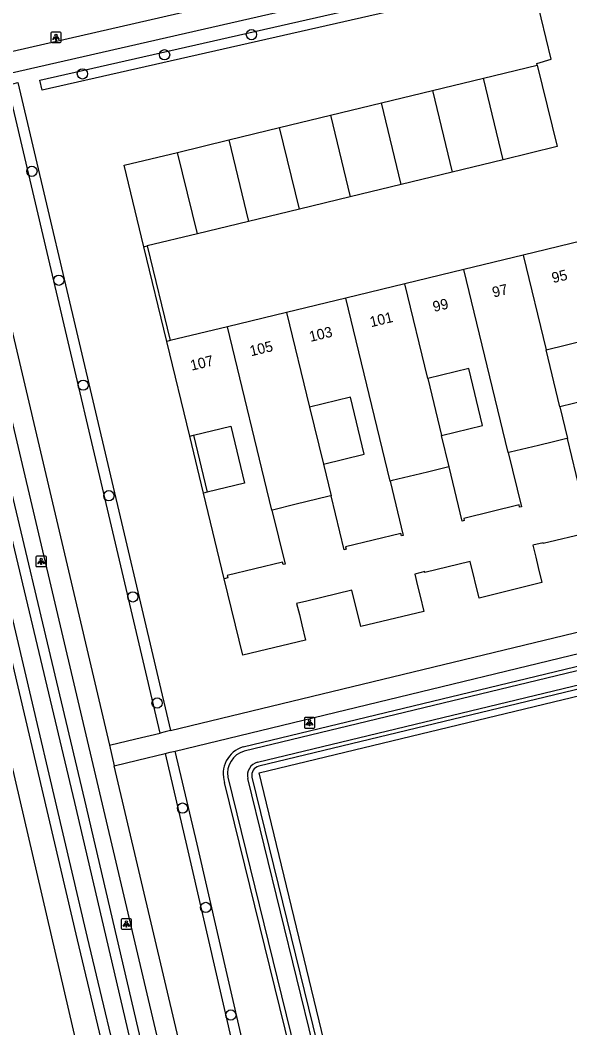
# Model space of a CAD drawing. Extents: x 156664 to 157568, y 383571 to 384421.
# Drawn here: x 156840.7 to 156893.1, y 383982.4 to 384078.5 of the extents above; entities that cross this region are included whole.
import ezdxf

# ---------------------------------------------------------------- set-up
doc = ezdxf.new("R2010")
doc.units = 0
for name, color, linetype in [('IMGEO_Boom', 7, 'Continuous'), ('IMGEO_Groenvoorziening', 7, 'Continuous'), ('IMGEO_Haag', 7, 'Continuous'), ('IMGEO_Hek', 7, 'Continuous'), ('IMGEO_Lichtpunt', 7, 'Continuous'), ('IMGEO_Muur', 7, 'Continuous'), ('IMGEO_Pand', 7, 'Continuous'), ('IMGEO_Pand_nummerreeks', 7, 'Continuous'), ('IMGEO_Rijbaan_lokaal_open', 7, 'Continuous'), ('IMGEO_Voetpad_open', 7, 'Continuous'), ('IMGEO_Waterloop', 7, 'Continuous')]:
    doc.layers.add(name, color=color, linetype=linetype)

msp = doc.modelspace()

# ---------------------------------------------------------------- linework, layer by layer
at = {"layer": 'IMGEO_Boom'}
for centre in [(156862.718, 384077.082), (156854.429, 384075.166), (156846.6, 384073.343), (156841.778, 384064.053), (156844.357, 384053.665), (156846.673, 384043.663), (156849.121, 384033.122), (156851.403, 384023.475), (156853.717, 384013.355), (156856.142, 384003.334), (156858.353, 383993.865), (156860.755, 383983.608)]:
    msp.add_circle(centre, 0.489, dxfattribs=at)
at = {"layer": 'IMGEO_Groenvoorziening'}
for points in [[(156825.282, 384070.084), (156860.158, 383919.98)], [(156836.685, 384046.556), (156846.808, 384004.086), (156865.113, 383925.704)], [(156861.939, 383925.229), (156862.009, 383925.475), (156861.632, 383926.582), (156857.459, 383943.277), (156846.139, 383990.769), (156837.808, 384026.146), (156834.432, 384042.083), (156834.089, 384043.235), (156833.431, 384045.96)], [(156861.913, 384009.165), (156971.048, 384035.487)], [(156965.9, 383938.498), (157002.117, 383942.318), (156972.167, 384033.813), (156964.844, 384031.779), (156863.418, 384007.321)], [(156953.099, 383937.896), (156882.007, 383929.988), (156863.465, 384006.689), (156971.911, 384032.865), (156984.848, 383993.384), (157001.305, 383943.16), (156963.71, 383939.037)], [(156894.839, 384029.59), (156890.551, 384028.557), (156890.532, 384028.636), (156889.551, 384028.393), (156889.825, 384027.259), (156890.057, 384026.288), (156890.416, 384024.833), (156884.421, 384023.366), (156883.565, 384026.863), (156879.257, 384025.815), (156879.24, 384025.884), (156878.288, 384025.653), (156878.565, 384024.519), (156878.792, 384023.543), (156879.155, 384022.083), (156873.159, 384020.64), (156872.305, 384024.119), (156868.004, 384023.082), (156867.027, 384022.845), (156867.284, 384021.787), (156867.53, 384020.811), (156867.878, 384019.352), (156861.885, 384017.92), (156860.113, 384025.202)], [(156862.766, 384006.287), (156881.463, 383929.99)], [(156878.907, 383929.526), (156860.158, 384005.773)]]:
    msp.add_lwpolyline(points, dxfattribs=at)
for centre, radius, start, end in [((156862.687, 384006.614), 2.666, 106.88763, 198.39883), ((156863.612, 384006.476), 0.867, 102.95087, 192.58127)]:
    msp.add_arc(centre, radius, start, end, dxfattribs=at)
at = {"layer": 'IMGEO_Haag'}
for points in [[(156842.768, 384071.784), (156842.547, 384072.759), (156888.556, 384083.206), (156888.777, 384082.231), (156842.768, 384071.784)], [(156854.016, 384010.495), (156839.474, 384072.282), (156840.447, 384072.511), (156854.988, 384010.73)], [(156854.475, 384008.544), (156856.565, 383999.666), (156874.225, 383922.969), (156874.338, 383922.477), (156874.835, 383922.525)], [(156954.665, 383931.279), (156875.116, 383923.557), (156857.538, 383999.895), (156855.447, 384008.779)]]:
    msp.add_lwpolyline(points, dxfattribs=at)
at = {"layer": 'IMGEO_Hek'}
msp.add_lwpolyline([(156953.099, 383937.896), (156882.007, 383929.988), (156863.465, 384006.689), (156971.911, 384032.865), (156984.848, 383993.384), (157001.305, 383943.16)], dxfattribs=at)
at = {"layer": 'IMGEO_Lichtpunt'}
for p, q in [((156843.576, 384077.235), (156843.576, 384076.428)), ((156843.576, 384077.235), (156843.576, 384076.428)), ((156844.478, 384077.33), (156843.67, 384077.33)), ((156844.478, 384077.33), (156843.67, 384077.33)), ((156844.572, 384076.428), (156844.572, 384077.235)), ((156844.572, 384076.428), (156844.572, 384077.235)), ((156843.67, 384076.334), (156844.478, 384076.334)), ((156843.67, 384076.334), (156844.478, 384076.334)), ((156842.167, 384027.259), (156842.167, 384026.452)), ((156842.167, 384027.259), (156842.167, 384026.452)), ((156843.069, 384027.354), (156842.261, 384027.354)), ((156843.069, 384027.354), (156842.261, 384027.354)), ((156843.163, 384026.452), (156843.163, 384027.259)), ((156843.163, 384026.452), (156843.163, 384027.259)), ((156842.261, 384026.358), (156843.069, 384026.358)), ((156842.261, 384026.358), (156843.069, 384026.358)), ((156867.761, 384011.871), (156867.761, 384011.064)), ((156867.761, 384011.871), (156867.761, 384011.064)), ((156868.663, 384011.966), (156867.855, 384011.966)), ((156868.663, 384011.966), (156867.855, 384011.966)), ((156868.757, 384011.064), (156868.757, 384011.871)), ((156868.757, 384011.064), (156868.757, 384011.871)), ((156867.855, 384010.97), (156868.663, 384010.97)), ((156867.855, 384010.97), (156868.663, 384010.97)), ((156850.293, 383992.685), (156850.293, 383991.878)), ((156850.293, 383992.685), (156850.293, 383991.878)), ((156851.195, 383992.78), (156850.387, 383992.78)), ((156851.195, 383992.78), (156850.387, 383992.78)), ((156851.289, 383991.878), (156851.289, 383992.685)), ((156851.289, 383991.878), (156851.289, 383992.685)), ((156850.387, 383991.784), (156851.195, 383991.784)), ((156850.387, 383991.784), (156851.195, 383991.784))]:
    msp.add_line(p, q, dxfattribs=at)
for points in [[(156843.95, 384076.899), (156843.989, 384076.871), (156843.801, 384076.609), (156843.763, 384076.636), (156843.95, 384076.899)], [(156844.052, 384076.851), (156844.099, 384076.851), (156844.099, 384076.529), (156844.052, 384076.529), (156844.052, 384076.851)], [(156844.162, 384076.871), (156844.2, 384076.898), (156844.387, 384076.636), (156844.348, 384076.608), (156844.162, 384076.871)], [(156842.541, 384026.923), (156842.58, 384026.895), (156842.392, 384026.633), (156842.354, 384026.66), (156842.541, 384026.923)], [(156842.643, 384026.875), (156842.69, 384026.875), (156842.69, 384026.553), (156842.643, 384026.553), (156842.643, 384026.875)], [(156842.753, 384026.895), (156842.791, 384026.922), (156842.978, 384026.66), (156842.939, 384026.632), (156842.753, 384026.895)], [(156868.135, 384011.535), (156868.174, 384011.507), (156867.986, 384011.245), (156867.948, 384011.272), (156868.135, 384011.535)], [(156868.237, 384011.487), (156868.284, 384011.487), (156868.284, 384011.165), (156868.237, 384011.165), (156868.237, 384011.487)], [(156868.347, 384011.507), (156868.385, 384011.534), (156868.572, 384011.272), (156868.533, 384011.244), (156868.347, 384011.507)], [(156850.667, 383992.349), (156850.706, 383992.321), (156850.518, 383992.059), (156850.48, 383992.086), (156850.667, 383992.349)], [(156850.769, 383992.301), (156850.816, 383992.301), (156850.816, 383991.979), (156850.769, 383991.979), (156850.769, 383992.301)], [(156850.879, 383992.321), (156850.917, 383992.348), (156851.104, 383992.086), (156851.065, 383992.058), (156850.879, 383992.321)]]:
    msp.add_lwpolyline(points, dxfattribs=at)
for centre in [(156844.075, 384077.033), (156842.666, 384027.057), (156868.26, 384011.669), (156850.792, 383992.483)]:
    msp.add_circle(centre, 0.0994, dxfattribs=at)
for centre, start, end in [((156843.67, 384077.235), 90, 180), ((156843.67, 384077.235), 90, 180), ((156844.478, 384077.235), 0, 90), ((156844.478, 384077.235), 0, 90), ((156843.67, 384076.428), 180, 270), ((156843.67, 384076.428), 180, 270), ((156844.478, 384076.428), 270, 0), ((156844.478, 384076.428), 270, 360), ((156842.261, 384027.259), 90, 180), ((156842.261, 384027.259), 90, 180), ((156843.069, 384027.259), 0, 90), ((156843.069, 384027.259), 0, 90), ((156842.261, 384026.452), 180, 270), ((156842.261, 384026.452), 180, 270), ((156843.069, 384026.452), 270, 0), ((156843.069, 384026.452), 270, 360), ((156867.855, 384011.871), 90, 180), ((156867.855, 384011.871), 90, 180), ((156868.663, 384011.871), 0, 90), ((156868.663, 384011.871), 0, 90), ((156867.855, 384011.064), 180, 270), ((156867.855, 384011.064), 180, 270), ((156868.663, 384011.064), 270, 0), ((156868.663, 384011.064), 270, 360), ((156850.387, 383992.685), 90, 180), ((156850.387, 383992.685), 90, 180), ((156851.195, 383992.685), 0, 90), ((156851.195, 383992.685), 0, 90), ((156850.387, 383991.878), 180, 270), ((156850.387, 383991.878), 180, 270), ((156851.195, 383991.878), 270, 0), ((156851.195, 383991.878), 270, 360)]:
    msp.add_arc(centre, 0.0946, start, end, dxfattribs=at)
at = {"layer": 'IMGEO_Muur'}
for points in [[(156854.648, 384047.837), (156852.46, 384056.86)], [(156852.781, 384056.937), (156854.969, 384047.915)], [(156858.151, 384033.36), (156856.828, 384038.808)], [(156857.188, 384038.894), (156858.51, 384033.448)]]:
    msp.add_lwpolyline(points, dxfattribs=at)
at = {"layer": 'IMGEO_Pand'}
for points in [[(156884.831, 384072.925), (156889.977, 384074.171)], [(156889.977, 384074.171), (156891.875, 384066.406), (156886.706, 384065.154)], [(156879.992, 384071.752), (156884.831, 384072.925)], [(156886.706, 384065.154), (156884.831, 384072.925)], [(156875.124, 384070.573), (156879.992, 384071.752)], [(156879.992, 384071.752), (156881.868, 384063.982)], [(156870.265, 384069.395), (156875.124, 384070.573)], [(156877.001, 384062.803), (156875.124, 384070.573)], [(156865.407, 384068.218), (156870.265, 384069.395)], [(156870.265, 384069.395), (156872.143, 384061.627)], [(156860.547, 384067.041), (156865.407, 384068.218)], [(156867.285, 384060.45), (156865.407, 384068.218)], [(156855.679, 384065.861), (156860.547, 384067.041)], [(156860.547, 384067.041), (156862.428, 384059.274)], [(156852.46, 384056.86), (156850.571, 384064.624), (156855.679, 384065.861)], [(156857.56, 384058.095), (156855.679, 384065.861)], [(156886.706, 384065.154), (156881.868, 384063.982)], [(156881.868, 384063.982), (156877.001, 384062.803)], [(156877.001, 384062.803), (156872.143, 384061.627)], [(156872.143, 384061.627), (156867.285, 384060.45)], [(156867.285, 384060.45), (156862.428, 384059.274)], [(156862.428, 384059.274), (156857.56, 384058.095)], [(156857.56, 384058.095), (156852.781, 384056.937)], [(156894.26, 384057.432), (156888.622, 384056.067)], [(156852.46, 384056.86), (156852.781, 384056.937)], [(156888.622, 384056.067), (156882.984, 384054.701)], [(156888.622, 384056.067), (156890.807, 384047.038)], [(156882.984, 384054.701), (156877.346, 384053.335)], [(156887.214, 384037.228), (156882.984, 384054.701)], [(156877.346, 384053.335), (156871.709, 384051.97)], [(156879.531, 384044.307), (156877.346, 384053.335)], [(156871.709, 384051.97), (156866.071, 384050.604)], [(156875.936, 384034.512), (156871.709, 384051.97)], [(156866.071, 384050.604), (156860.433, 384049.238)], [(156866.071, 384050.604), (156868.257, 384041.576)], [(156860.433, 384049.238), (156854.969, 384047.915)], [(156864.676, 384031.745), (156860.433, 384049.238)], [(156854.969, 384047.915), (156854.648, 384047.837)], [(156856.828, 384038.808), (156854.648, 384047.837)], [(156890.807, 384047.038), (156894.71, 384047.98), (156896.031, 384042.54), (156892.125, 384041.59)], [(156892.125, 384041.59), (156890.807, 384047.038)], [(156880.85, 384038.859), (156884.755, 384039.808), (156883.434, 384045.249), (156879.531, 384044.307)], [(156879.531, 384044.307), (156880.85, 384038.859)], [(156869.577, 384036.128), (156873.479, 384037.077), (156872.158, 384042.518), (156868.257, 384041.576)], [(156868.257, 384041.576), (156869.577, 384036.128)], [(156892.125, 384041.59), (156892.851, 384038.588)], [(156857.188, 384038.894), (156860.736, 384039.751), (156862.057, 384034.31), (156858.51, 384033.448)], [(156898.483, 384039.975), (156899.739, 384034.784), (156899.571, 384034.743), (156899.522, 384034.965), (156894.235, 384033.695), (156894.286, 384033.473), (156894.099, 384033.43), (156892.851, 384038.588)], [(156856.828, 384038.808), (156857.188, 384038.894)], [(156881.572, 384035.877), (156880.85, 384038.859)], [(156892.851, 384038.588), (156892.674, 384038.545), (156891.521, 384038.267), (156890.103, 384037.925), (156887.402, 384037.273), (156887.214, 384037.228)], [(156887.214, 384037.228), (156888.461, 384032.074), (156888.288, 384032.032), (156888.236, 384032.244), (156882.959, 384030.955), (156883.007, 384030.744), (156882.826, 384030.698), (156881.572, 384035.877)], [(156869.577, 384036.128), (156870.306, 384033.116)], [(156881.572, 384035.877), (156881.404, 384035.836), (156879.649, 384035.411), (156878.826, 384035.212), (156876.127, 384034.558), (156875.936, 384034.512)], [(156875.936, 384034.512), (156877.19, 384029.332), (156877.025, 384029.29), (156876.967, 384029.517), (156871.689, 384028.239), (156871.74, 384028.012), (156871.553, 384027.964), (156870.306, 384033.116)], [(156858.51, 384033.448), (156858.151, 384033.36)], [(156860.113, 384025.202), (156858.151, 384033.36)], [(156870.306, 384033.116), (156870.137, 384033.075), (156866.856, 384032.276), (156864.861, 384031.79), (156864.676, 384031.745)], [(156864.676, 384031.745), (156865.924, 384026.6), (156865.746, 384026.556), (156865.691, 384026.781), (156860.413, 384025.519), (156860.467, 384025.284), (156860.113, 384025.202)]]:
    msp.add_lwpolyline(points, dxfattribs=at)
at = {"layer": 'IMGEO_Rijbaan_lokaal_open'}
msp.add_lwpolyline([(156889.977, 384074.171), (156889.94, 384074.329), (156891.301, 384074.755), (156888.906, 384084.645)], dxfattribs=at)
at = {"layer": 'IMGEO_Voetpad_open'}
for points in [[(156888.427, 384086.586), (156811.028, 384068.852)], [(156888.906, 384084.645), (156834.367, 384072.163)], [(156832.423, 384071.718), (156867.866, 383921.383), (156867.979, 383920.714)], [(156834.367, 384072.163), (156849.171, 384009.324)], [(156855.447, 384008.779), (156971.462, 384036.848)], [(156854.988, 384010.73), (156961.888, 384036.567)], [(156849.171, 384009.324), (156851.701, 384009.935), (156854.016, 384010.495)], [(156854.988, 384010.73), (156854.502, 384010.612), (156854.016, 384010.495)], [(156849.171, 384009.324), (156849.631, 384007.372)], [(156849.631, 384007.372), (156851.846, 384007.908), (156854.475, 384008.544)], [(156854.475, 384008.544), (156854.961, 384008.661), (156855.447, 384008.779)], [(156870.13, 383920.364), (156849.631, 384007.372)]]:
    msp.add_lwpolyline(points, dxfattribs=at)
at = {"layer": 'IMGEO_Waterloop'}
for points in [[(156834.425, 384045.9), (156835.009, 384043.483), (156835.356, 384042.318), (156838.738, 384026.354), (156847.066, 383990.989), (156858.384, 383943.503), (156862.546, 383926.851), (156862.901, 383925.812), (156863.002, 383925.486)], [(156845.881, 384003.867), (156835.811, 384046.116)], [(156971.146, 384035.093), (156862.02, 384008.774)], [(156863.303, 384007.711), (156964.742, 384032.172), (156972.432, 384034.308), (157002.659, 383941.967), (156965.949, 383938.095)], [(156860.453, 384006.276), (156879.298, 383929.636)], [(156881.069, 383929.893), (156862.381, 384006.152)], [(156864.119, 383925.774), (156845.881, 384003.867)]]:
    msp.add_lwpolyline(points, dxfattribs=at)
for centre, radius, start, end in [((156862.689, 384006.614), 2.261, 107.20779, 188.59196), ((156863.613, 384006.475), 1.274, 104.10158, 194.69788)]:
    msp.add_arc(centre, radius, start, end, dxfattribs=at)

# ---------------------------------------------------------------- texts
at = {"layer": 'IMGEO_Pand_nummerreeks'}
for s, p in [('95', (156891.482, 384053.385)), ('97', (156885.811, 384052.011)), ('99', (156880.137, 384050.636)), ('101', (156874.128, 384049.181)), ('103', (156868.35, 384047.781)), ('105', (156862.679, 384046.408)), ('107', (156857.008, 384045.034))]:
    msp.add_text(s, height=1, rotation=13.61921, dxfattribs=at).set_placement(p)

doc.saveas('drawing.dxf')
